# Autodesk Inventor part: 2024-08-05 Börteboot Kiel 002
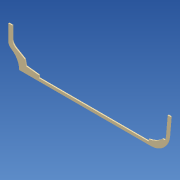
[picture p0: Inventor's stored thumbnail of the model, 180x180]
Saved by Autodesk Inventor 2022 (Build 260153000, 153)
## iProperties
Created: 2024-08
Part Number: 2024-08-05 Börteboot Kiel 002
Material: Generisch
Document SubType Name: Modeling
Designer: i3meg
Density: 1 g/cm^3
Appearance: Beige
Author: i3meg
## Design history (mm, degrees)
sketch "Skizze3"
  geometry: L1 (0, 65)-(0, 145); L2 (45, 0)-(590, 0); L3 (-497.082, 0)-(875.493, 0) reference; L4 (0, -139.186)-(0, 363.947) reference; L5 (-13.298, 65)-(13.298, 65); L6 (45, 6.802)-(45, -6.802); L7 (649.229, 70)-(679.411, 70); L8 (590, 31.664)-(590, 6.805); L9 (664.371, 70)-(670.933, 145); L10 (655, 0)-(655, 200.893); L11 (658.887, 145)-(652.325, 70); L12 (590, 12)-(126, 12); L13 (16, 80)-(16, 145); L14 (0, 145)-(16, 145); L15 (330, 0)-(330, 292.071); L16 (670.933, 145)-(658.887, 145); L17 (0, 77.576)-(0, -67.31); L18 (68, 50)-(73, 28); L19 (73, 28)-(126, 22); L20 (126, 22)-(126, 12); L21 (580, 12)-(580, 20); L22 (647.567, 50)-(637.567, 50); L23 (68, 50)-(16, 80); A1 r 62.199 centre (590.268, 74.198) between (590, 12) and (652.325, 70); A2 r 74.508 centre (590, 74.508) between (590, 0) and (664.371, 70); A3 r 100 centre (565.071, 118.879) between (580, 20) and (637.567, 50); A4 r 68.783 centre (-23.781, 0.459) between (45, 0) and (0, 65); 6 further points
  constraints: 42 end point, 9 point on circle, 9 point on line, 6 vertical, 4 centre point, 4 midpoint, 3 horizontal, 3 perpendicular, 1 collinear, 1 symmetric about line, 1 tangent
  dimensions: "d7" = 145 distance of point (0, 0) L1.end; "d11" = 45 distance between parallel lines of L4 L6; "d23" = 12 distance between parallel lines of L2 L12; "d31" = 330 distance between parallel lines of L4 L15; "d34" = 12 distance between parallel lines of L9 L11; "d39" = 590 distance between parallel lines of L4 L8; "d40" = 70 distance between parallel lines of L3 L7; "d41" = 85 deg angle of L3 L9; "d42" = 145 distance between parallel lines of L3 L16; "d45" = 65 distance between parallel lines of L3 L5; "d92" = 126 distance between parallel lines of L4 L20; "d95" = 22 distance from line of L2 L19.end; "d96" = 73 distance from line of L4 L18.end; "d97" = 68 distance from line of L4 L18.start; "d99" = 50 distance from line of L3 L18.start; "d101" = 10 distance between parallel lines of L21 L8; "d102" = 10 distance of L22.start L22.end; "d103" = 50 distance between parallel lines of L3 L22; "d104" = 8 distance from line of L12 L21.end; "d105" = 100 radius of A3; "d108" = 65 distance of L13.start L13.end; "d109" = 16 distance between parallel lines of L1 L13
extrude "Extrusion9" new body sketch "Skizze3" distance "d90" = 4.5; taper "d91" = 0 deg
fillet "Rundung9" dims "d93" = 24
fillet "Rundung11" dims "d107" = 30
node "Volumenkörper4"
